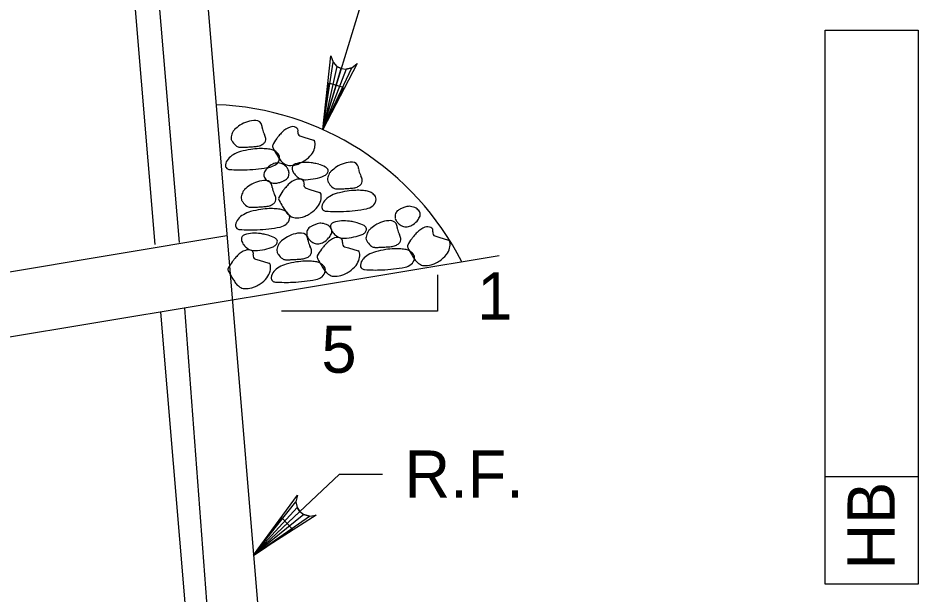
# Model space of a CAD drawing. Extents: x 638340 to 640242, y 295465 to 298435.
# Drawn here: x 639122.9 to 639180.1, y 297065.1 to 297101.7 of the extents above; entities that cross this region are included whole.
import ezdxf

# ---------------------------------------------------------------- set-up
doc = ezdxf.new("R2010")
doc.units = 0
for name, color, linetype in [('Level 3', 7, 'Continuous'), ('Level 5', 7, 'Continuous'), ('Level 8', 7, 'Continuous'), ('Level 9', 7, 'Continuous')]:
    doc.layers.add(name, color=color, linetype=linetype)

msp = doc.modelspace()

# ---------------------------------------------------------------- linework, layer by layer
at = {"layer": 'Level 3'}
for p, q in [((639142.311, 297094.609), (639151.481, 297124.707)), ((639174.244, 297100.942), (639180.137, 297100.942)), ((639174.244, 297072.542), (639174.244, 297100.942)), ((639180.137, 297100.942), (639180.137, 297065.71)), ((639137.917, 297067.542), (639143.373, 297072.692)), ((639143.373, 297072.692), (639146.102, 297072.692)), ((639174.244, 297065.71), (639174.244, 297072.542)), ((639180.137, 297072.542), (639174.244, 297072.542)), ((639180.137, 297065.71), (639174.244, 297065.71))]:
    msp.add_line(p, q, dxfattribs=at)
for points in [[(639142.311, 297094.609), (639142.833, 297099.312), (639142.966, 297098.896), (639143.209, 297098.63), (639143.492, 297098.487), (639143.806, 297098.447), (639144.159, 297098.534), (639144.5, 297098.805), (639142.311, 297094.609), (639144.159, 297098.534), (639143.806, 297098.447), (639142.311, 297094.609), (639143.492, 297098.487), (639143.209, 297098.63), (639142.311, 297094.609), (639142.966, 297098.896)], [(639149.601, 297085.368), (639149.601, 297083.064), (639139.697, 297083.064)], [(639137.917, 297067.542), (639140.701, 297071.37), (639140.61, 297070.941), (639140.691, 297070.588), (639140.866, 297070.326), (639141.119, 297070.135), (639141.467, 297070.035), (639141.899, 297070.101), (639137.917, 297067.542), (639141.467, 297070.035), (639141.119, 297070.135), (639137.917, 297067.542), (639140.866, 297070.326), (639140.691, 297070.588), (639137.917, 297067.542), (639140.61, 297070.941)]]:
    msp.add_lwpolyline(points, dxfattribs=at)
for points in [[(639143.64, 297097.285), (639142.7, 297097.57), (639142.311, 297094.609)], [(639140.398, 297069.205), (639139.722, 297069.92), (639137.917, 297067.539)]]:
    msp.add_lwpolyline(points, close=True, dxfattribs=at)
at = {"layer": 'Level 5'}
for p, q in [((639129.785, 297109.669), (639131.648, 297087.312)), ((639131.344, 297109.437), (639133.178, 297087.441)), ((639132.008, 297083.008), (639135.551, 297040.483)), ((639133.526, 297083.261), (639138.668, 297014.786))]:
    msp.add_line(p, q, dxfattribs=at)
at = {"layer": 'Level 8'}
for points in [[(639140.864, 297094.216), (639141.107, 297094.139), (639141.716, 297093.947)], [(639141.255, 297090.885), (639141.498, 297090.808), (639142.109, 297090.614)], [(639149.439, 297087.849), (639149.684, 297087.772), (639150.294, 297087.578)], [(639143.698, 297087.167), (639143.943, 297087.09), (639144.552, 297086.896)], [(639138.032, 297086.381), (639138.277, 297086.304), (639138.886, 297086.11)]]:
    msp.add_lwpolyline(points, dxfattribs=at)
for centre, radius, start, end in [((639138.7, 297092.453), 2.938, 124.1443, 132.7374), ((639138.046, 297093.417), 1.773, 89.5772, 124.1443), ((639138.057, 297094.796), 0.394, 11.4529, 89.5772), ((639137.123, 297094.607), 1.346, 6.1004, 11.4529), ((639137.744, 297093.894), 1.281, 153.538, 168.4897), ((639137.05, 297094.239), 0.506, 132.7374, 153.538), ((639139.362, 297094.846), 0.905, 186.1004, 192.6291), ((639139.777, 297094.939), 1.331, 192.6291, 208.6753), ((639138.001, 297093.968), 0.694, 6.391, 28.6753), ((639143.74, 297090.628), 5.536, 136.4562, 139.6491), ((639140.667, 297093.549), 1.296, 109.6635, 136.4562), ((639140.4, 297094.296), 0.502, 65.9597, 109.6635), ((639140.511, 297094.544), 0.231, 342.3569, 65.9597), ((639140.926, 297094.412), 0.205, 162.3569, 252.4715), ((639136.792, 297094.088), 0.31, 168.4897, 199.1639), ((639137.021, 297094.167), 0.553, 199.1639, 207.4728), ((639137.314, 297094.319), 0.882, 207.4728, 214.0468), ((639137.456, 297094.415), 1.054, 214.0468, 234.0353), ((639138.091, 297094.282), 0.724, 291.5731, 310.9894), ((639138.32, 297094.018), 0.375, 310.9894, 338.0834), ((639138.349, 297094.007), 0.344, 338.0834, 6.391), ((639142.183, 297092.018), 3.451, 144.1424, 152.1777), ((639141.652, 297092.402), 2.796, 139.6491, 144.1424), ((639141.673, 297093.806), 0.148, 9.0416, 72.4715), ((639140.894, 297093.682), 0.937, 344.9373, 9.0416), ((639137.551, 297091.466), 1.805, 104.9239, 120.8473), ((639137.052, 297093.859), 0.366, 234.0353, 268.2715), ((639137.143, 297096.857), 3.365, 268.2715, 270.9097), ((639138.753, 297086.956), 6.473, 99.0416, 104.9239), ((639137.057, 297102.22), 8.729, 270.9097, 272.5478), ((639136.81, 297107.778), 14.293, 272.5478, 273.846), ((639138.405, 297089.142), 4.259, 91.7881, 99.0416), ((639136.902, 297106.409), 12.921, 273.846, 275.2114), ((639137.983, 297094.555), 1.017, 275.2114, 291.5731), ((639138.403, 297089.206), 4.195, 86.0442, 91.7881), ((639138.499, 297090.591), 2.807, 79.021, 86.0442), ((639138.901, 297092.663), 0.697, 58.4341, 79.021), ((639139.251, 297093.566), 0.136, 152.1777, 193.5774), ((639139.588, 297093.647), 0.482, 193.5774, 207.4728), ((639144.908, 297096.413), 6.478, 207.4728, 211.2525), ((639138.784, 297092.473), 0.919, 40.5338, 58.4341), ((639140.693, 297093.736), 1.144, 321.7572, 344.9373), ((639136.831, 297092.272), 0.71, 139.2037, 172.3458), ((639137.323, 297091.847), 1.361, 120.8473, 139.2037), ((639138.972, 297092.878), 0.603, 309.5539, 349.0625), ((639154.17, 297102.034), 17.312, 211.2525, 212.2356), ((639139.205, 297092.833), 0.365, 349.0625, 40.5338), ((639142.715, 297094.811), 3.77, 212.2356, 214.3424), ((639140.076, 297093.007), 0.574, 214.3424, 227.6953), ((639140.881, 297093.892), 1.77, 227.6953, 235.2847), ((639141.227, 297090.204), 2.322, 81.3134, 106.8084), ((639139.667, 297094.956), 2.759, 295.7443, 303.0692), ((639140.216, 297094.113), 1.752, 303.0692, 321.7572), ((639144.179, 297090.767), 1.773, 89.5772, 124.1443), ((639144.189, 297092.146), 0.394, 11.4529, 89.5772), ((639136.371, 297092.334), 0.246, 172.3458, 230.2635), ((639136.413, 297092.384), 0.312, 230.2635, 266.2346), ((639137.071, 297102.386), 10.335, 266.2346, 272.3841), ((639137.082, 297102.11), 10.059, 272.3841, 280.7777), ((639139.735, 297091.265), 1.297, 136.4654, 149.2422), ((639139.731, 297091.269), 1.292, 117.4803, 136.4654), ((639138.8, 297093.086), 0.872, 280.7777, 309.5539), ((639139.453, 297091.804), 0.689, 91.376, 117.4803), ((639139.453, 297091.813), 0.68, 65.3457, 91.376), ((639139.412, 297091.723), 0.779, 41.057, 65.3457), ((639140.197, 297092.905), 0.568, 235.2847, 266.0442), ((639139.314, 297091.638), 0.909, 27.4728, 41.057), ((639139.724, 297091.851), 0.446, 8.0357, 27.4728), ((639140.257, 297093.77), 1.436, 266.0442, 285.2565), ((639140.635, 297092.164), 0.275, 106.8084, 186.6218), ((639140.942, 297092.2), 0.584, 186.6218, 200.3491), ((639141.06, 297092.244), 0.71, 200.3491, 212.797), ((639140.28, 297093.685), 1.348, 285.2565, 295.7443), ((639140.649, 297086.421), 6.15, 78.4814, 81.3134), ((639141.422, 297090.215), 2.278, 73.8272, 78.4814), ((639141.463, 297090.356), 2.13, 61.1605, 73.8272), ((639142.319, 297091.911), 0.356, 29.8544, 61.1605), ((639142.282, 297092.039), 0.375, 317.8475, 347.2445), ((639142.469, 297091.997), 0.183, 347.2445, 29.8544), ((639143.182, 297091.589), 0.506, 132.7374, 153.538), ((639144.833, 297089.803), 2.938, 124.1443, 132.7374), ((639143.256, 297091.957), 1.346, 6.1004, 11.4529), ((639145.494, 297092.196), 0.905, 186.1004, 192.6291), ((639145.91, 297092.289), 1.331, 192.6291, 208.6753), ((639138.902, 297091.727), 0.339, 171.9761, 209.5935), ((639138.976, 297091.717), 0.414, 149.2422, 171.9761), ((639139.128, 297091.856), 0.599, 209.5935, 237.6667), ((639138.627, 297093.733), 2.671, 297.4803, 299.831), ((639139.755, 297091.766), 0.403, 299.831, 337.0418), ((639141.059, 297090.217), 1.296, 109.6635, 136.4562), ((639139.597, 297091.833), 0.575, 337.0418, 8.0357), ((639141.384, 297092.452), 1.095, 212.797, 230.2213), ((639140.792, 297090.964), 0.502, 65.9597, 109.6635), ((639141.199, 297092.23), 0.806, 230.2213, 250.5601), ((639141.197, 297092.225), 0.8, 250.5601, 271.915), ((639140.902, 297091.212), 0.231, 342.3569, 65.9597), ((639141.102, 297095.073), 3.65, 271.915, 281.8686), ((639141.212, 297094.547), 3.113, 281.8686, 292.039), ((639142.196, 297092.116), 0.49, 292.039, 317.8475), ((639142.925, 297091.437), 0.31, 168.4897, 199.1639), ((639143.876, 297091.243), 1.281, 153.538, 168.4897), ((639144.133, 297091.317), 0.694, 6.391, 28.6753), ((639144.481, 297091.356), 0.344, 338.0834, 6.391), ((639139.342, 297088.639), 2.938, 124.1443, 132.7374), ((639138.688, 297089.603), 1.773, 89.5772, 124.1443), ((639138.698, 297090.982), 0.394, 11.4529, 89.5772), ((639139.355, 297092.213), 1.022, 237.6667, 259.0544), ((639137.765, 297090.793), 1.346, 6.1004, 11.4529), ((639140.004, 297091.033), 0.905, 186.1004, 192.6291), ((639140.419, 297091.126), 1.331, 192.6291, 208.6753), ((639139.286, 297091.858), 0.66, 259.0544, 285.7584), ((639138.161, 297095.842), 4.8, 285.7584, 288.5059), ((639139.285, 297092.485), 1.26, 288.5059, 293.8705), ((639142.044, 297089.07), 2.796, 139.6491, 144.1424), ((639139.337, 297092.369), 1.133, 293.8705, 297.4803), ((639144.132, 297087.296), 5.536, 136.4562, 139.6491), ((639141.317, 297091.08), 0.205, 162.3569, 252.4715), ((639143.154, 297091.517), 0.553, 199.1639, 207.4728), ((639143.446, 297091.669), 0.882, 207.4728, 214.0468), ((639143.588, 297091.765), 1.054, 214.0468, 234.0353), ((639143.184, 297091.208), 0.366, 234.0353, 268.2715), ((639143.275, 297094.206), 3.365, 268.2715, 270.9097), ((639143.19, 297099.569), 8.729, 270.9097, 272.5478), ((639142.942, 297105.127), 14.293, 272.5478, 273.846), ((639143.034, 297103.759), 12.921, 273.846, 275.2114), ((639144.116, 297091.904), 1.017, 275.2114, 291.5731), ((639144.223, 297091.632), 0.724, 291.5731, 310.9894), ((639144.453, 297091.368), 0.375, 310.9894, 338.0834), ((639137.434, 297090.274), 0.31, 168.4897, 199.1639), ((639138.386, 297090.08), 1.281, 153.538, 168.4897), ((639137.692, 297090.425), 0.506, 132.7374, 153.538), ((639138.643, 297090.154), 0.694, 6.391, 28.6753), ((639139.643, 297090.233), 0.136, 152.1777, 193.5774), ((639142.575, 297088.686), 3.451, 144.1424, 152.1777), ((639142.065, 297090.474), 0.148, 9.0416, 72.4715), ((639141.285, 297090.35), 0.937, 344.9373, 9.0416), ((639143.456, 297089.197), 1.361, 120.8473, 139.2037), ((639143.683, 297088.815), 1.805, 104.9239, 120.8473), ((639144.885, 297084.305), 6.473, 99.0416, 104.9239), ((639144.537, 297086.492), 4.259, 91.7881, 99.0416), ((639144.535, 297086.556), 4.195, 86.0442, 91.7881), ((639144.631, 297087.94), 2.807, 79.021, 86.0442), ((639145.033, 297090.012), 0.697, 58.4341, 79.021), ((639144.917, 297089.823), 0.919, 40.5338, 58.4341), ((639145.337, 297090.182), 0.365, 349.0625, 40.5338), ((639137.663, 297090.353), 0.553, 199.1639, 207.4728), ((639137.956, 297090.506), 0.882, 207.4728, 214.0468), ((639138.098, 297090.601), 1.054, 214.0468, 234.0353), ((639137.694, 297090.045), 0.366, 234.0353, 268.2715), ((639137.785, 297093.043), 3.365, 268.2715, 270.9097), ((639137.699, 297098.406), 8.729, 270.9097, 272.5478), ((639137.452, 297103.964), 14.293, 272.5478, 273.846), ((639137.544, 297102.596), 12.921, 273.846, 275.2114), ((639138.625, 297090.741), 1.017, 275.2114, 291.5731), ((639138.733, 297090.468), 0.724, 291.5731, 310.9894), ((639138.962, 297090.204), 0.375, 310.9894, 338.0834), ((639138.991, 297090.193), 0.344, 338.0834, 6.391), ((639139.979, 297090.315), 0.482, 193.5774, 207.4728), ((639145.3, 297093.081), 6.478, 207.4728, 211.2525), ((639154.561, 297098.702), 17.312, 211.2525, 212.2356), ((639140.608, 297090.78), 1.752, 303.0692, 321.7572), ((639141.085, 297090.404), 1.144, 321.7572, 344.9373), ((639142.503, 297089.684), 0.246, 172.3458, 230.2635), ((639142.963, 297089.622), 0.71, 139.2037, 172.3458), ((639144.932, 297090.435), 0.872, 280.7777, 309.5539), ((639145.104, 297090.227), 0.603, 309.5539, 349.0625), ((639149.135, 297085.154), 4.8, 108.8812, 111.6288), ((639147.795, 297089.072), 0.66, 82.1773, 108.8812), ((639147.746, 297088.713), 1.022, 60.7895, 82.1773), ((639137.965, 297088.033), 1.361, 120.8473, 139.2037), ((639138.193, 297087.652), 1.805, 104.9239, 120.8473), ((639139.395, 297083.142), 6.473, 99.0416, 104.9239), ((639139.047, 297085.329), 4.259, 91.7881, 99.0416), ((639139.045, 297085.392), 4.195, 86.0442, 91.7881), ((639139.141, 297086.777), 2.807, 79.021, 86.0442), ((639139.543, 297088.849), 0.697, 58.4341, 79.021), ((639139.426, 297088.659), 0.919, 40.5338, 58.4341), ((639143.107, 297091.479), 3.77, 212.2356, 214.3424), ((639140.467, 297089.675), 0.574, 214.3424, 227.6953), ((639141.273, 297090.56), 1.77, 227.6953, 235.2847), ((639139.847, 297089.019), 0.365, 349.0625, 40.5338), ((639140.588, 297089.572), 0.568, 235.2847, 266.0442), ((639140.671, 297090.353), 1.348, 285.2565, 295.7443), ((639140.058, 297091.624), 2.759, 295.7443, 303.0692), ((639142.545, 297089.734), 0.312, 230.2635, 266.2346), ((639143.203, 297099.736), 10.335, 266.2346, 272.3841), ((639143.215, 297099.459), 10.059, 272.3841, 280.7777), ((639147.483, 297089.08), 0.575, 160.1647, 191.1585), ((639147.322, 297089.138), 0.403, 122.9538, 160.1647), ((639148.555, 297087.235), 2.671, 120.6031, 122.9538), ((639147.772, 297088.559), 1.133, 116.9933, 120.6031), ((639147.83, 297088.445), 1.26, 111.6288, 116.9933), ((639147.953, 297089.082), 0.599, 32.7163, 60.7895), ((639148.171, 297089.223), 0.339, 355.0989, 32.7163), ((639148.097, 297089.229), 0.414, 332.365, 355.0989), ((639137.013, 297088.52), 0.246, 172.3458, 230.2635), ((639137.472, 297088.459), 0.71, 139.2037, 172.3458), ((639139.442, 297089.272), 0.872, 280.7777, 309.5539), ((639139.614, 297089.064), 0.603, 309.5539, 349.0625), ((639140.648, 297090.437), 1.436, 266.0442, 285.2565), ((639142.216, 297087.367), 1.26, 111.6288, 116.9933), ((639143.521, 297084.076), 4.8, 108.8812, 111.6288), ((639142.181, 297087.994), 0.66, 82.1773, 108.8812), ((639142.131, 297087.635), 1.022, 60.7895, 82.1773), ((639142.338, 297088.004), 0.599, 32.7163, 60.7895), ((639143.079, 297088.447), 0.275, 106.8084, 186.6218), ((639143.671, 297086.487), 2.322, 81.3134, 106.8084), ((639143.093, 297082.703), 6.15, 78.4814, 81.3134), ((639143.866, 297086.497), 2.278, 73.8272, 78.4814), ((639143.907, 297086.639), 2.13, 61.1605, 73.8272), ((639146.623, 297087.049), 1.773, 89.5772, 124.1443), ((639146.633, 297088.428), 0.394, 11.4529, 89.5772), ((639147.357, 297089.055), 0.446, 191.1585, 210.5956), ((639147.755, 297089.29), 0.909, 210.5956, 224.1798), ((639147.662, 297089.2), 0.779, 224.1798, 248.4685), ((639147.625, 297089.117), 0.689, 274.4988, 300.6031), ((639147.318, 297089.636), 1.292, 300.6031, 319.5882), ((639147.314, 297089.639), 1.297, 319.5882, 332.365), ((639137.054, 297088.571), 0.312, 230.2635, 266.2346), ((639137.713, 297098.573), 10.335, 266.2346, 272.3841), ((639138.005, 297085.701), 2.322, 81.3134, 106.8084), ((639137.724, 297098.296), 10.059, 272.3841, 280.7777), ((639137.427, 297081.917), 6.15, 78.4814, 81.3134), ((639140.956, 297086.263), 1.773, 89.5772, 124.1443), ((639140.967, 297087.642), 0.394, 11.4529, 89.5772), ((639141.869, 297088.002), 0.575, 160.1647, 191.1585), ((639141.707, 297088.06), 0.403, 122.9538, 160.1647), ((639142.941, 297086.157), 2.671, 120.6031, 122.9538), ((639142.158, 297087.481), 1.133, 116.9933, 120.6031), ((639141.699, 297088.561), 1.297, 319.5882, 332.365), ((639143.386, 297088.482), 0.584, 186.6218, 200.3491), ((639143.504, 297088.526), 0.71, 200.3491, 212.797), ((639142.557, 297088.145), 0.339, 355.0989, 32.7163), ((639142.483, 297088.151), 0.414, 332.365, 355.0989), ((639143.828, 297088.735), 1.095, 212.797, 230.2213), ((639144.64, 297088.399), 0.49, 292.039, 317.8475), ((639144.763, 297088.193), 0.356, 29.8544, 61.1605), ((639144.726, 297088.321), 0.375, 317.8475, 347.2445), ((639146.32, 297087.526), 1.281, 153.538, 168.4897), ((639144.913, 297088.279), 0.183, 347.2445, 29.8544), ((639145.626, 297087.871), 0.506, 132.7374, 153.538), ((639147.277, 297086.085), 2.938, 124.1443, 132.7374), ((639145.7, 297088.239), 1.346, 6.1004, 11.4529), ((639147.939, 297088.478), 0.905, 186.1004, 192.6291), ((639148.354, 297088.571), 1.331, 192.6291, 208.6753), ((639147.626, 297089.107), 0.68, 248.4685, 274.4988), ((639152.317, 297084.26), 5.536, 136.4562, 139.6491), ((639149.244, 297087.181), 1.296, 109.6635, 136.4562), ((639148.976, 297087.928), 0.502, 65.9597, 109.6635), ((639149.087, 297088.176), 0.231, 342.3569, 65.9597), ((639149.502, 297088.044), 0.205, 162.3569, 252.4715), ((639137.413, 297087.661), 0.275, 106.8084, 186.6218), ((639137.72, 297087.696), 0.584, 186.6218, 200.3491), ((639137.838, 297087.74), 0.71, 200.3491, 212.797), ((639138.2, 297085.711), 2.278, 73.8272, 78.4814), ((639138.241, 297085.853), 2.13, 61.1605, 73.8272), ((639139.097, 297087.407), 0.356, 29.8544, 61.1605), ((639139.059, 297087.536), 0.375, 317.8475, 347.2445), ((639139.247, 297087.493), 0.183, 347.2445, 29.8544), ((639139.96, 297087.085), 0.506, 132.7374, 153.538), ((639141.61, 297085.299), 2.938, 124.1443, 132.7374), ((639141.742, 297087.977), 0.446, 191.1585, 210.5956), ((639140.033, 297087.453), 1.346, 6.1004, 11.4529), ((639142.141, 297088.212), 0.909, 210.5956, 224.1798), ((639142.272, 297087.692), 0.905, 186.1004, 192.6291), ((639142.688, 297087.785), 1.331, 192.6291, 208.6753), ((639142.048, 297088.122), 0.779, 224.1798, 248.4685), ((639142.011, 297088.029), 0.68, 248.4685, 274.4988), ((639142.011, 297088.039), 0.689, 274.4988, 300.6031), ((639146.576, 297083.578), 5.536, 136.4562, 139.6491), ((639141.704, 297088.558), 1.292, 300.6031, 319.5882), ((639143.503, 297086.499), 1.296, 109.6635, 136.4562), ((639143.236, 297087.246), 0.502, 65.9597, 109.6635), ((639143.643, 297088.512), 0.806, 230.2213, 250.5601), ((639143.641, 297088.507), 0.8, 250.5601, 271.915), ((639143.346, 297087.494), 0.231, 342.3569, 65.9597), ((639143.761, 297087.362), 0.205, 162.3569, 252.4715), ((639143.546, 297091.355), 3.65, 271.915, 281.8686), ((639143.656, 297090.829), 3.113, 281.8686, 292.039), ((639145.369, 297087.719), 0.31, 168.4897, 199.1639), ((639145.598, 297087.799), 0.553, 199.1639, 207.4728), ((639145.89, 297087.951), 0.882, 207.4728, 214.0468), ((639146.032, 297088.047), 1.054, 214.0468, 234.0353), ((639146.897, 297087.65), 0.375, 310.9894, 338.0834), ((639146.577, 297087.599), 0.694, 6.391, 28.6753), ((639146.925, 297087.638), 0.344, 338.0834, 6.391), ((639150.76, 297085.65), 3.451, 144.1424, 152.1777), ((639150.229, 297086.034), 2.796, 139.6491, 144.1424), ((639150.25, 297087.438), 0.148, 9.0416, 72.4715), ((639149.47, 297087.314), 0.937, 344.9373, 9.0416), ((639137.836, 297085.713), 1.296, 109.6635, 136.4562), ((639138.162, 297087.949), 1.095, 212.797, 230.2213), ((639137.569, 297086.461), 0.502, 65.9597, 109.6635), ((639137.977, 297087.727), 0.806, 230.2213, 250.5601), ((639137.975, 297087.721), 0.8, 250.5601, 271.915), ((639137.68, 297086.708), 0.231, 342.3569, 65.9597), ((639137.88, 297090.569), 3.65, 271.915, 281.8686), ((639137.99, 297090.043), 3.113, 281.8686, 292.039), ((639138.974, 297087.613), 0.49, 292.039, 317.8475), ((639139.702, 297086.934), 0.31, 168.4897, 199.1639), ((639140.654, 297086.74), 1.281, 153.538, 168.4897), ((639139.932, 297087.013), 0.553, 199.1639, 207.4728), ((639140.911, 297086.814), 0.694, 6.391, 28.6753), ((639141.259, 297086.853), 0.344, 338.0834, 6.391), ((639145.019, 297084.968), 3.451, 144.1424, 152.1777), ((639144.488, 297085.352), 2.796, 139.6491, 144.1424), ((639144.509, 297086.756), 0.148, 9.0416, 72.4715), ((639146.127, 297085.098), 1.805, 104.9239, 120.8473), ((639145.629, 297087.491), 0.366, 234.0353, 268.2715), ((639145.719, 297090.488), 3.365, 268.2715, 270.9097), ((639147.329, 297080.588), 6.473, 99.0416, 104.9239), ((639145.634, 297095.851), 8.729, 270.9097, 272.5478), ((639145.387, 297101.41), 14.293, 272.5478, 273.846), ((639146.981, 297082.774), 4.259, 91.7881, 99.0416), ((639145.479, 297100.041), 12.921, 273.846, 275.2114), ((639146.56, 297088.186), 1.017, 275.2114, 291.5731), ((639146.979, 297082.838), 4.195, 86.0442, 91.7881), ((639146.667, 297087.914), 0.724, 291.5731, 310.9894), ((639147.075, 297084.222), 2.807, 79.021, 86.0442), ((639147.477, 297086.294), 0.697, 58.4341, 79.021), ((639147.828, 297087.197), 0.136, 152.1777, 193.5774), ((639148.164, 297087.279), 0.482, 193.5774, 207.4728), ((639153.485, 297090.045), 6.478, 207.4728, 211.2525), ((639147.361, 297086.105), 0.919, 40.5338, 58.4341), ((639149.27, 297087.368), 1.144, 321.7572, 344.9373), ((639138.822, 297084.566), 2.796, 139.6491, 144.1424), ((639140.91, 297082.792), 5.536, 136.4562, 139.6491), ((639138.095, 297086.576), 0.205, 162.3569, 252.4715), ((639140.224, 297087.165), 0.882, 207.4728, 214.0468), ((639140.366, 297087.261), 1.054, 214.0468, 234.0353), ((639139.962, 297086.705), 0.366, 234.0353, 268.2715), ((639140.053, 297089.702), 3.365, 268.2715, 270.9097), ((639139.968, 297095.065), 8.729, 270.9097, 272.5478), ((639139.72, 297100.624), 14.293, 272.5478, 273.846), ((639141.315, 297081.988), 4.259, 91.7881, 99.0416), ((639139.812, 297099.255), 12.921, 273.846, 275.2114), ((639140.893, 297087.4), 1.017, 275.2114, 291.5731), ((639141.313, 297082.052), 4.195, 86.0442, 91.7881), ((639141.001, 297087.128), 0.724, 291.5731, 310.9894), ((639141.231, 297086.864), 0.375, 310.9894, 338.0834), ((639141.409, 297083.437), 2.807, 79.021, 86.0442), ((639142.087, 297086.516), 0.136, 152.1777, 193.5774), ((639142.423, 297086.597), 0.482, 193.5774, 207.4728), ((639147.744, 297089.363), 6.478, 207.4728, 211.2525), ((639143.529, 297086.686), 1.144, 321.7572, 344.9373), ((639143.729, 297086.632), 0.937, 344.9373, 9.0416), ((639145.407, 297085.904), 0.71, 139.2037, 172.3458), ((639145.9, 297085.479), 1.361, 120.8473, 139.2037), ((639147.548, 297086.51), 0.603, 309.5539, 349.0625), ((639162.746, 297095.666), 17.312, 211.2525, 212.2356), ((639147.781, 297086.465), 0.365, 349.0625, 40.5338), ((639151.292, 297088.443), 3.77, 212.2356, 214.3424), ((639148.652, 297086.639), 0.574, 214.3424, 227.6953), ((639148.243, 297088.588), 2.759, 295.7443, 303.0692), ((639148.792, 297087.744), 1.752, 303.0692, 321.7572), ((639136.421, 297085.73), 0.136, 152.1777, 193.5774), ((639136.757, 297085.811), 0.482, 193.5774, 207.4728), ((639139.353, 297084.182), 3.451, 144.1424, 152.1777), ((639138.842, 297085.97), 0.148, 9.0416, 72.4715), ((639138.063, 297085.846), 0.937, 344.9373, 9.0416), ((639140.233, 297084.693), 1.361, 120.8473, 139.2037), ((639140.461, 297084.312), 1.805, 104.9239, 120.8473), ((639141.663, 297079.802), 6.473, 99.0416, 104.9239), ((639141.811, 297085.509), 0.697, 58.4341, 79.021), ((639141.694, 297085.319), 0.919, 40.5338, 58.4341), ((639157.005, 297094.984), 17.312, 211.2525, 212.2356), ((639145.551, 297087.761), 3.77, 212.2356, 214.3424), ((639142.115, 297085.679), 0.365, 349.0625, 40.5338), ((639143.052, 297087.062), 1.752, 303.0692, 321.7572), ((639144.947, 297085.966), 0.246, 172.3458, 230.2635), ((639144.989, 297086.016), 0.312, 230.2635, 266.2346), ((639145.647, 297096.018), 10.335, 266.2346, 272.3841), ((639145.659, 297095.742), 10.059, 272.3841, 280.7777), ((639147.377, 297086.717), 0.872, 280.7777, 309.5539), ((639149.458, 297087.524), 1.77, 227.6953, 235.2847), ((639148.773, 297086.536), 0.568, 235.2847, 266.0442), ((639148.833, 297087.401), 1.436, 266.0442, 285.2565), ((639148.856, 297087.317), 1.348, 285.2565, 295.7443), ((639142.077, 297088.578), 6.478, 207.4728, 211.2525), ((639151.339, 297094.198), 17.312, 211.2525, 212.2356), ((639137.385, 297086.277), 1.752, 303.0692, 321.7572), ((639137.863, 297085.9), 1.144, 321.7572, 344.9373), ((639139.281, 297085.18), 0.246, 172.3458, 230.2635), ((639139.741, 297085.118), 0.71, 139.2037, 172.3458), ((639141.71, 297085.932), 0.872, 280.7777, 309.5539), ((639141.882, 297085.724), 0.603, 309.5539, 349.0625), ((639142.911, 297085.957), 0.574, 214.3424, 227.6953), ((639143.717, 297086.842), 1.77, 227.6953, 235.2847), ((639143.032, 297085.854), 0.568, 235.2847, 266.0442), ((639143.092, 297086.72), 1.436, 266.0442, 285.2565), ((639143.115, 297086.635), 1.348, 285.2565, 295.7443), ((639142.502, 297087.906), 2.759, 295.7443, 303.0692), ((639139.885, 297086.975), 3.77, 212.2356, 214.3424), ((639137.245, 297085.172), 0.574, 214.3424, 227.6953), ((639138.051, 297086.057), 1.77, 227.6953, 235.2847), ((639137.366, 297085.069), 0.568, 235.2847, 266.0442), ((639137.426, 297085.934), 1.436, 266.0442, 285.2565), ((639137.449, 297085.849), 1.348, 285.2565, 295.7443), ((639136.836, 297087.12), 2.759, 295.7443, 303.0692), ((639139.323, 297085.23), 0.312, 230.2635, 266.2346), ((639139.981, 297095.232), 10.335, 266.2346, 272.3841), ((639139.992, 297094.956), 10.059, 272.3841, 280.7777)]:
    msp.add_arc(centre, radius, start, end, dxfattribs=at)
at = {"layer": 'Level 9'}
for p, q in [((639128.903, 297175.704), (639140.3, 297038.948)), ((639136.225, 297087.859), (639110.484, 297083.569)), ((639153.517, 297086.593), (639110.484, 297079.421))]:
    msp.add_line(p, q, dxfattribs=at)
msp.add_arc((639134.832, 297077.911), 18.297, 26.9324, 87.7453, dxfattribs=at)

# ---------------------------------------------------------------- texts
at = {"layer": 'Level 3'}
for s, height, p in [('1', 3, (639152.134, 297082.532)), ('5', 3, (639142.23, 297079.149)), ('R.F.', 3.0001, (639147.509, 297071.207))]:
    msp.add_text(s, height=height, dxfattribs=at).set_placement(p)
msp.add_text('HB', height=3.0001, rotation=90, dxfattribs=at).set_placement((639178.656, 297066.641))

doc.saveas('drawing.dxf')
